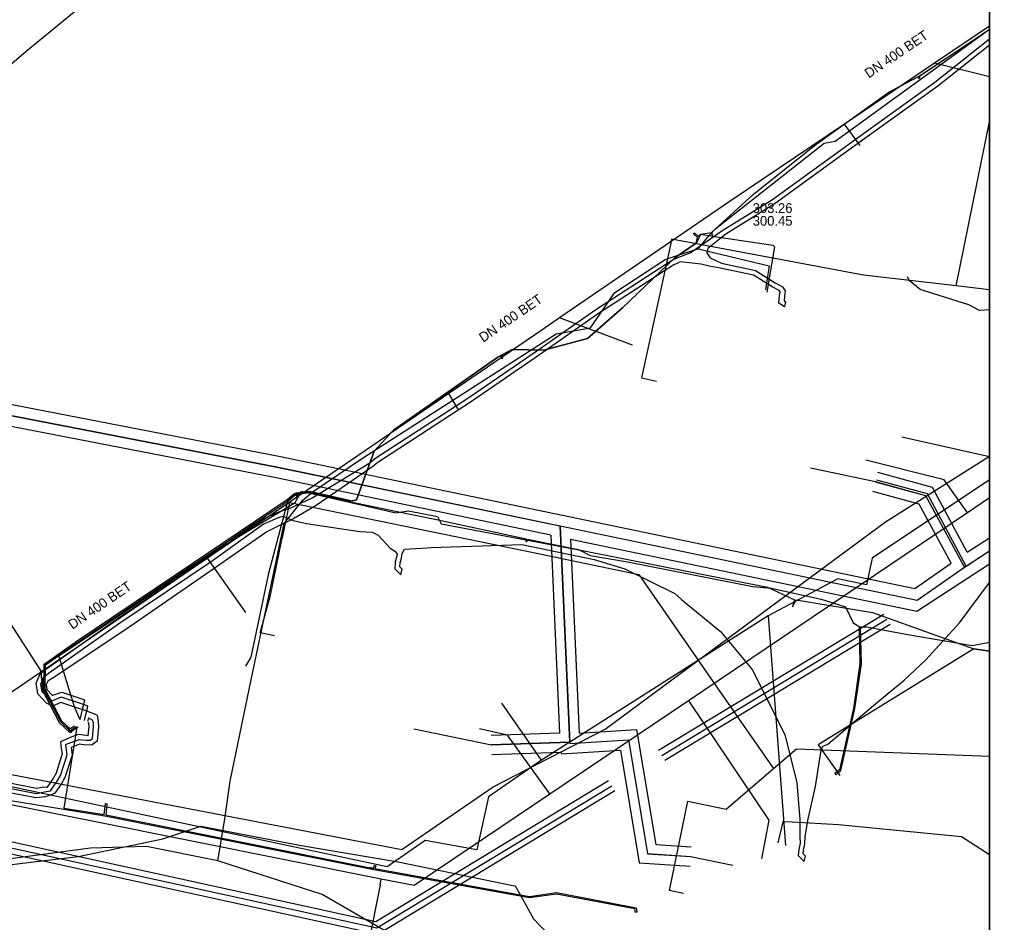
# Model space of a CAD drawing. Extents: x -598233 to -596890, y -1157848 to -1156431.
# Drawn here: x -596970.3 to -596890.5, y -1156694.6 to -1156620.3 of the extents above; entities that cross this region are included whole.
import ezdxf

# ---------------------------------------------------------------- set-up
doc = ezdxf.new("R2010")
doc.units = 0
for name, color, linetype in [('Vrstva 12', 7, 'Continuous'), ('Vrstva 13', 7, 'Continuous'), ('Vrstva 16', 7, 'Continuous'), ('Vrstva 19', 7, 'Continuous'), ('Vrstva 37', 7, 'Continuous'), ('Vrstva 38', 7, 'Continuous'), ('Vrstva 42', 7, 'Continuous'), ('Vrstva 55', 7, 'Continuous'), ('Vrstva 58', 7, 'Continuous'), ('Vrstva 60', 7, 'Continuous'), ('Vrstva 9', 7, 'Continuous'), ('zajmove_uzemi', 7, 'Continuous')]:
    doc.layers.add(name, color=color, linetype=linetype)

msp = doc.modelspace()

# ---------------------------------------------------------------- linework, layer by layer
at = {"layer": 'Vrstva 12'}
for p, q in [((-596890.462, -1156628.613), (-596890.48, -1156628.7)), ((-596890.462, -1156642.532), (-596893.2, -1156642.21))]:
    msp.add_line(p, q, dxfattribs=at)
for points in [[(-596893.2, -1156642.21), (-596890.48, -1156628.7)], [(-596916.727, -1156638.834), (-596919.1, -1156649.78), (-596917.88, -1156650.03)], [(-596893.2, -1156642.21), (-596900.84, -1156641.31), (-596916.626, -1156638.369), (-596916.727, -1156638.834)], [(-596948.6, -1156662.66), (-596948.05, -1156660.02), (-596928.14, -1156664.12), (-596919.32, -1156665.94), (-596913.09, -1156674.93), (-596908.53, -1156681.51), (-596908.24, -1156681.92)], [(-596949.31, -1156670.99), (-596950.49, -1156670.75), (-596949.64, -1156667.65), (-596948.66, -1156662.96), (-596948.6, -1156662.66)], [(-596908.24, -1156681.92), (-596906.34, -1156680.3), (-596890.462, -1156680.897)], [(-596915.64, -1156692.19), (-596916.79, -1156691.95), (-596915.3, -1156684.6), (-596912.15, -1156685.24), (-596908.24, -1156681.92)], [(-596978.48, -1156691.48), (-596975.31, -1156690.33), (-596965.47, -1156689.14), (-596958.49, -1156687.7), (-596955.37, -1156686.64), (-596947.26, -1156688.21), (-596945.47, -1156688.51)], [(-596945.47, -1156688.51), (-596939.14, -1156689.58), (-596929.7, -1156691.53)], [(-596929.7, -1156691.53), (-596929.49, -1156691.57), (-596928.9, -1156692.64)], [(-596928.9, -1156692.64), (-596927.99, -1156694.27), (-596924.9, -1156697.52), (-596921.41, -1156700.73), (-596919.34, -1156702.7), (-596918.68, -1156703.63), (-596917.78, -1156704.19), (-596916.85, -1156706.16), (-596914.16, -1156711.34), (-596910.89, -1156714.39), (-596904.56, -1156718.91), (-596900.16, -1156722.49), (-596897.928, -1156726.658)]]:
    msp.add_lwpolyline(points, dxfattribs=at)
at = {"layer": 'Vrstva 13'}
for p, q in [((-596940.522, -1156691), (-596999.171, -1156679.242)), ((-596940.617, -1156691.482), (-596940.522, -1156691))]:
    msp.add_line(p, q, dxfattribs=at)
for points in [[(-596892.293, -1156660.877), (-596892.343, -1156660.8), (-596894.197, -1156658.147), (-596900.657, -1156656.545)], [(-596890.462, -1156659.644), (-596892.293, -1156660.877), (-596915.238, -1156676.335), (-596926.647, -1156684.02), (-596934.627, -1156689.398), (-596937.81, -1156691.544), (-596940.522, -1156691)], [(-596915.238, -1156676.335), (-596915.152, -1156676.461), (-596908.641, -1156686.153), (-596909.219, -1156689.349)], [(-596926.647, -1156684.02), (-596926.732, -1156683.886), (-596930.119, -1156679.171), (-596932.423, -1156678.632)], [(-596940.617, -1156691.482), (-596948.106, -1156729.131), (-596948.339, -1156730.315), (-596948.53, -1156731.238)]]:
    msp.add_lwpolyline(points, dxfattribs=at)
at = {"layer": 'Vrstva 16'}
msp.add_line((-596897.68, -1156654.63), (-596890.462, -1156656.246), dxfattribs=at)
for points in [[(-596890.462, -1156658.167), (-596900.13, -1156664.59), (-596900.58, -1156666.8), (-596902.94, -1156666.3), (-596908.67, -1156669.34), (-596927.34, -1156681.23), (-596931.7, -1156684.23), (-596932.66, -1156688.6), (-596936.9, -1156687.83), (-596940.03, -1156690), (-596981.04, -1156681.27), (-596997, -1156677.6), (-597016.06, -1156671.9), (-597015.61, -1156669.9)], [(-596908.67, -1156669.34), (-596907.25, -1156688.25)], [(-596927.34, -1156681.23), (-596930.61, -1156676.54)]]:
    msp.add_lwpolyline(points, dxfattribs=at)
at = {"layer": 'Vrstva 19'}
msp.add_lwpolyline([(-596990.71, -1156678.66), (-596990.29, -1156678.69), (-596990.15, -1156678.37), (-596980.83, -1156680.51), (-596938.83, -1156688.56), (-596931.31, -1156683.41), (-596922.1, -1156678.66), (-596905.13, -1156666.11), (-596899.02, -1156661.61), (-596890.462, -1156656.215)], dxfattribs=at)
at = {"layer": 'Vrstva 37'}
for p, q in [((-596899.863, -1156658.336), (-596905.212, -1156657.21)), ((-596925.801, -1156661.951), (-596925.013, -1156679.762)), ((-596925.801, -1156661.951), (-596925.006, -1156679.756)), ((-596892.541, -1156665.348), (-596890.462, -1156664)), ((-596892.39, -1156665.247), (-596890.462, -1156663.999)), ((-596917.435, -1156680.833), (-596898.915, -1156669.625)), ((-596931.449, -1156679.981), (-596937.839, -1156678.674)), ((-596925.013, -1156679.762), (-596931.449, -1156679.981)), ((-596925.013, -1156679.762), (-596931.449, -1156679.981)), ((-596915.061, -1156689.154), (-596911.603, -1156689.859))]:
    msp.add_line(p, q, dxfattribs=at)
for points in [[(-597000.648, -1156655.849), (-596996.215, -1156656.976), (-596994.547, -1156648.298), (-596948.98, -1156657.107), (-596925.801, -1156661.951)], [(-597000.648, -1156655.849), (-596996.215, -1156656.976), (-596994.547, -1156648.298), (-596948.978, -1156657.138), (-596925.826, -1156661.946)], [(-596892.39, -1156665.247), (-596895.582, -1156659.321), (-596899.74, -1156658.191)], [(-596892.541, -1156665.348), (-596895.705, -1156659.466), (-596899.863, -1156658.336)], [(-596892.541, -1156665.348), (-596895.705, -1156659.466), (-596899.863, -1156658.336)], [(-596925.826, -1156661.946), (-596925.039, -1156679.73), (-596931.475, -1156679.949)], [(-596925.801, -1156661.951), (-596896.426, -1156668.05), (-596892.541, -1156665.348)], [(-596925.801, -1156661.951), (-596896.426, -1156668.05), (-596892.541, -1156665.348)], [(-596925.013, -1156679.762), (-596925.003, -1156679.859), (-596920.178, -1156679.547), (-596918.606, -1156688.918), (-596915.061, -1156689.154)], [(-596925.013, -1156679.762), (-596925.002, -1156679.861), (-596920.178, -1156679.547), (-596918.606, -1156688.918), (-596915.061, -1156689.154)], [(-596925.006, -1156679.756), (-596924.996, -1156679.853), (-596920.171, -1156679.541), (-596918.599, -1156688.912), (-596915.054, -1156689.148)], [(-596994.927, -1156683.194), (-596990.833, -1156684.091), (-596940.89, -1156695.028), (-596921.559, -1156683.329)]]:
    msp.add_lwpolyline(points, dxfattribs=at)
at = {"layer": 'Vrstva 38'}
for p, q in [((-596926.568, -1156662.71), (-596925.848, -1156678.989)), ((-596892.295, -1156664.116), (-596890.462, -1156662.927)), ((-596924.952, -1156663.046), (-596924.246, -1156679.008)), ((-596924.952, -1156663.046), (-596896.461, -1156668.962)), ((-596896.461, -1156668.962), (-596890.462, -1156665.073)), ((-596917.694, -1156680.405), (-596899.174, -1156669.197)), ((-596898.656, -1156670.053), (-596917.176, -1156681.261)), ((-596925.848, -1156678.989), (-596931.476, -1156679.181)), ((-596925.732, -1156680.587), (-596931.422, -1156680.781))]:
    msp.add_line(p, q, dxfattribs=at)
for points in [[(-597000.426, -1156654.977), (-596996.919, -1156655.868), (-596995.261, -1156647.243), (-596948.803, -1156656.225), (-596925.617, -1156661.07)], [(-596926.568, -1156662.71), (-596949.157, -1156657.989), (-596993.833, -1156649.353), (-596995.511, -1156658.084), (-597000.907, -1156656.712)], [(-596892.295, -1156664.116), (-596895.163, -1156658.784), (-596899.653, -1156657.564)], [(-596893.632, -1156665.01), (-596896.247, -1156660.148), (-596900.073, -1156659.108)], [(-596925.618, -1156661.07), (-596896.622, -1156667.09), (-596893.632, -1156665.01)], [(-596924.246, -1156679.008), (-596919.509, -1156678.702), (-596917.922, -1156688.162), (-596915.008, -1156688.356)], [(-596925.732, -1156680.587), (-596925.72, -1156680.707), (-596920.847, -1156680.392), (-596919.29, -1156689.674), (-596915.114, -1156689.952)], [(-596994.82, -1156682.706), (-596940.978, -1156694.497), (-596921.818, -1156682.901)], [(-596921.3, -1156683.757), (-596940.802, -1156695.559), (-596995.034, -1156683.682)]]:
    msp.add_lwpolyline(points, dxfattribs=at)
at = {"layer": 'Vrstva 42'}
for p, q in [((-596925.8, -1156661.95), (-596925.01, -1156679.76)), ((-596892.39, -1156665.25), (-596890.462, -1156664.005)), ((-596925.01, -1156679.76), (-596931.45, -1156679.98))]:
    msp.add_line(p, q, dxfattribs=at)
for points in [[(-596963.909, -1156677.528), (-596964.756, -1156677.187), (-596965.117, -1156677.042), (-596965.123, -1156677.04), (-596965.406, -1156676.965), (-596966.895, -1156676.47), (-596967.558, -1156676.78), (-596968.077, -1156676.525), (-596968.787, -1156675.768), (-596968.909, -1156674.892), (-596968.581, -1156674.128), (-596968.148, -1156673.759), (-596962.174, -1156669.532), (-596954.836, -1156664.613), (-596950.431, -1156661.447), (-596948.935, -1156660.802), (-596948.026, -1156660.486), (-596946.204, -1156659.652), (-596941.45, -1156656.746), (-596941.041, -1156656.408), (-596933.309, -1156651.387), (-596927.713, -1156647.549), (-596922.859, -1156644.15), (-596916.632, -1156640.105), (-596916.164, -1156639.903), (-596915.114, -1156639.47), (-596912.404, -1156637.606), (-596908.329, -1156635.083), (-596901.831, -1156630.371), (-596894.964, -1156625.441), (-596890.462, -1156621.888)], [(-596890.462, -1156622.397), (-596894.724, -1156625.761), (-596901.597, -1156630.695), (-596908.105, -1156635.415), (-596912.176, -1156637.936), (-596913.658, -1156639.122), (-596913.743, -1156639.495), (-596913.455, -1156639.906), (-596912.525, -1156640.345), (-596909.731, -1156640.933), (-596908.1, -1156641.961), (-596907.51, -1156642.289), (-596907.271, -1156642.618), (-596907.345, -1156643.04), (-596907.377, -1156643.421), (-596907.257, -1156643.509), (-596907.312, -1156643.754)], [(-596907.312, -1156643.754), (-596907.351, -1156643.936), (-596907.793, -1156643.611), (-596907.743, -1156642.99), (-596907.695, -1156642.716), (-596907.782, -1156642.595), (-596908.304, -1156642.305), (-596909.883, -1156641.309), (-596912.631, -1156640.731), (-596913.537, -1156640.57), (-596914.198, -1156640.416), (-596915.923, -1156640.231), (-596916.118, -1156640.323), (-596916.44, -1156640.457), (-596922.635, -1156644.482), (-596927.485, -1156647.877), (-596933.087, -1156651.719), (-596940.803, -1156656.73), (-596941.212, -1156657.068), (-596945.868, -1156660.273), (-596947.801, -1156661.4), (-596947.898, -1156661.444), (-596948.726, -1156661.82), (-596949.928, -1156662.441), (-596954.255, -1156665.458), (-596961.62, -1156670.534), (-596967.61, -1156674.49), (-596967.967, -1156674.727), (-596968.085, -1156675.002), (-596968.029, -1156675.406), (-596967.597, -1156675.867), (-596967.542, -1156675.882), (-596966.81, -1156675.626), (-596965.146, -1156676.188), (-596964.928, -1156676.259), (-596965.022, -1156676.65), (-596965.117, -1156677.042), (-596965.319, -1156677.879)], [(-597000.65, -1156655.85), (-596996.22, -1156656.98), (-596994.55, -1156648.3), (-596948.98, -1156657.14), (-596925.83, -1156661.95)], [(-596892.39, -1156665.25), (-596895.58, -1156659.32), (-596899.74, -1156658.19)], [(-596892.54, -1156665.35), (-596895.7, -1156659.47), (-596899.86, -1156658.34)], [(-596964.947, -1156677.968), (-596964.818, -1156677.461), (-596964.756, -1156677.187), (-596964.662, -1156676.77), (-596965.022, -1156676.65), (-596966.858, -1156676.038), (-596967.563, -1156676.326), (-596967.837, -1156676.196), (-596968.408, -1156675.587), (-596968.53, -1156674.976), (-596968.25, -1156674.372), (-596967.888, -1156674.063), (-596961.948, -1156669.862), (-596954.608, -1156664.941), (-596950.233, -1156661.797), (-596948.85, -1156661.198), (-596948.61, -1156661.145), (-596947.898, -1156661.444), (-596947.756, -1156661.504), (-596946.657, -1156661.744), (-596942.284, -1156662.42), (-596941.279, -1156662.473), (-596940.775, -1156662.698), (-596939.786, -1156663.772), (-596939.404, -1156664.028), (-596939.202, -1156664.247), (-596939.256, -1156664.524), (-596939.37, -1156664.921), (-596939.39, -1156665.469), (-596938.909, -1156665.985), (-596938.849, -1156665.7), (-596938.803, -1156665.499), (-596938.984, -1156665.315), (-596938.972, -1156664.985), (-596938.862, -1156664.604), (-596938.789, -1156664.209), (-596938.616, -1156663.868), (-596936.74, -1156663.765), (-596936.405, -1156663.712), (-596928.958, -1156663.488), (-596923.008, -1156664.706), (-596920.488, -1156665.474), (-596916.374, -1156667.504), (-596915.816, -1156668.004), (-596912.601, -1156670.636), (-596910.011, -1156673.762), (-596907.32, -1156679.108), (-596906.327, -1156683.082), (-596906.066, -1156686.097), (-596906.066, -1156687.516), (-596906.057, -1156688.051), (-596906.158, -1156688.576), (-596906.203, -1156689.064), (-596905.729, -1156689.57), (-596905.675, -1156689.329)], [(-596925.83, -1156661.95), (-596925.04, -1156679.73), (-596931.47, -1156679.95)], [(-596925.8, -1156661.95), (-596896.43, -1156668.05), (-596892.54, -1156665.35)], [(-596905.675, -1156689.329), (-596905.617, -1156689.107), (-596905.789, -1156688.922), (-596905.762, -1156688.632), (-596905.659, -1156688.095), (-596905.635, -1156687.541), (-596905.421, -1156686.188), (-596904.795, -1156683.387), (-596904.335, -1156680.403), (-596904.189, -1156680.072), (-596903.761, -1156679.911), (-596899.657, -1156676.416), (-596897.498, -1156674.632), (-596895.75, -1156672.985), (-596892.928, -1156669.909), (-596890.462, -1156666.603)], [(-596963.909, -1156677.528), (-596963.803, -1156678.065), (-596963.785, -1156678.489), (-596963.909, -1156679.645), (-596964.317, -1156679.968), (-596964.824, -1156679.989), (-596965.337, -1156679.912), (-596966.043, -1156680.174), (-596965.962, -1156680.805), (-596966.549, -1156682.646), (-596966.86, -1156683.19), (-596967.411, -1156683.964), (-596968.155, -1156684.231), (-596968.95, -1156684.323), (-596974.442, -1156683.278)], [(-596974.38, -1156682.883), (-596968.888, -1156683.954), (-596968.225, -1156683.837), (-596967.737, -1156683.732), (-596967.19, -1156682.942), (-596966.917, -1156682.484), (-596966.371, -1156680.771), (-596966.454, -1156680.184), (-596966.481, -1156679.939), (-596966.364, -1156679.88), (-596965.387, -1156679.525), (-596964.81, -1156679.588), (-596964.463, -1156679.574), (-596964.289, -1156679.436), (-596964.186, -1156678.476), (-596964.2, -1156678.142), (-596964.28, -1156677.918), (-596964.605, -1156677.779), (-596964.685, -1156678.029)], [(-596964.668, -1156678.12), (-596964.619, -1156678.131), (-596964.597, -1156678.219), (-596964.587, -1156678.463), (-596964.669, -1156679.227), (-596964.796, -1156679.187), (-596965.436, -1156679.117), (-596965.971, -1156679.312), (-596966.904, -1156679.709), (-596966.859, -1156680.251), (-596966.772, -1156680.697), (-596967.263, -1156682.29), (-596967.524, -1156682.722), (-596968.049, -1156683.465), (-596968.295, -1156683.443), (-596968.884, -1156683.547), (-596974.318, -1156682.488)], [(-596966.261, -1156678.479), (-596966.222, -1156678.758), (-596966.047, -1156678.951), (-596965.975, -1156678.863)], [(-596925.01, -1156679.76), (-596925, -1156679.85), (-596920.17, -1156679.54), (-596918.6, -1156688.91), (-596915.05, -1156689.15)], [(-596925.01, -1156679.76), (-596925, -1156679.86), (-596920.18, -1156679.55), (-596918.61, -1156688.92), (-596915.06, -1156689.15)]]:
    msp.add_lwpolyline(points, dxfattribs=at)
at = {"layer": 'Vrstva 55'}
for points in [[(-596972.3, -1156625.05), (-596969.73, -1156622.9), (-596962.75, -1156617.14)], [(-596965.6, -1156678.47), (-596966.12, -1156678.8), (-596966.89, -1156678.08), (-596968.289, -1156675.407), (-596968.27, -1156673.329), (-596965.819, -1156671.587), (-596965.61, -1156671.68), (-596965.716, -1156671.515), (-596957.343, -1156665.89), (-596948.256, -1156659.782), (-596947.62, -1156659.267), (-596947.433, -1156659.553), (-596947.35, -1156659.57), (-596947.333, -1156659.487), (-596947.51, -1156659.216), (-596946.387, -1156659.089), (-596942.884, -1156659.887), (-596942.55, -1156659.8), (-596941.11, -1156655.79), (-596939.5, -1156654.08), (-596930.93, -1156648.06), (-596930.713, -1156647.948), (-596930.62, -1156648.142), (-596930.54, -1156648.17), (-596930.512, -1156648.09), (-596930.607, -1156647.892), (-596929.76, -1156647.44), (-596927.13, -1156647.48), (-596923.56, -1156646.54), (-596920.66, -1156644), (-596916.33, -1156639.87), (-596914.61, -1156638.69), (-596914.505, -1156638.217), (-596914.796, -1156637.955), (-596914.8, -1156637.87), (-596914.715, -1156637.866), (-596914.441, -1156638.114), (-596914.23, -1156637.96), (-596913.34, -1156637.81), (-596909.93, -1156634.68), (-596909.2, -1156634.12), (-596904.76, -1156630.57), (-596898.74, -1156626.26), (-596896.374, -1156624.999), (-596896.285, -1156625.103), (-596896.2, -1156625.11), (-596896.193, -1156625.025), (-596896.269, -1156624.937), (-596891.76, -1156621.97), (-596890.462, -1156621.081)], [(-596890.462, -1156644.171), (-596891.28, -1156644.22), (-596892.17, -1156643.77), (-596896.17, -1156642.49), (-596897.08, -1156641.76), (-596897.23, -1156641.46)], [(-596965.748, -1156678.422), (-596966.106, -1156678.649), (-596966.793, -1156678.006), (-596968.169, -1156675.378), (-596968.15, -1156673.391), (-596965.686, -1156671.639), (-596959.12, -1156667.228), (-596957.277, -1156665.99), (-596954.134, -1156663.877), (-596951.051, -1156661.805), (-596948.184, -1156659.878), (-596947.833, -1156659.595), (-596947.516, -1156659.338), (-596946.393, -1156659.211), (-596943.023, -1156659.979), (-596939.48, -1156660.7), (-596935.96, -1156661.41), (-596928.609, -1156663.017), (-596928.625, -1156663.205), (-596928.57, -1156663.27), (-596928.505, -1156663.215), (-596928.491, -1156663.042), (-596924.29, -1156663.88), (-596923.32, -1156664.37), (-596920.25, -1156664.91), (-596909.95, -1156666.92), (-596908.43, -1156667.07), (-596904.33, -1156667.97), (-596902.33, -1156668.6), (-596901.69, -1156669.92), (-596901.201, -1156670.222), (-596901.13, -1156673.296), (-596901.659, -1156676.959), (-596902.814, -1156682.006), (-596903.18, -1156682.296), (-596903.19, -1156682.38), (-596903.106, -1156682.39), (-596902.706, -1156682.074), (-596901.541, -1156676.981), (-596901.01, -1156673.304), (-596901.08, -1156670.258), (-596900.58, -1156670.24), (-596897.18, -1156670.88), (-596891.91, -1156671.78), (-596890.462, -1156671.509)], [(-596965.29, -1156677.9), (-596965.75, -1156676.84), (-596967.04, -1156672.65), (-596953.544, -1156663.61), (-596947.613, -1156660.015), (-596947.07, -1156659.08), (-596939.31, -1156660.87), (-596938.27, -1156660.72), (-596935.89, -1156661.17), (-596935.59, -1156661.77), (-596923.81, -1156664), (-596908.75, -1156666.98), (-596906.52, -1156668.03), (-596906.67, -1156668.62), (-596906.37, -1156668.03), (-596900.11, -1156669.07), (-596891.76, -1156672.05), (-596890.462, -1156672.259)], [(-596965.6, -1156678.47), (-596966.12, -1156678.8), (-596966.89, -1156678.08), (-596968.289, -1156675.407), (-596968.54, -1156673.84), (-596974.43, -1156664.72), (-596974.89, -1156664.58), (-596978.41, -1156663.08), (-596979.9, -1156662.59), (-596982.63, -1156664.4), (-596985.57, -1156668.83), (-596989.58, -1156673.24), (-596991.79, -1156675.42), (-596994.05, -1156677.85), (-596993.75, -1156680.67), (-596993.714, -1156680.787)], [(-596965.453, -1156678.519), (-596966.134, -1156678.951), (-596966.987, -1156678.154), (-596968.336, -1156675.576), (-596968.54, -1156673.84), (-596974.43, -1156664.72)], [(-596890.462, -1156672.259), (-596891.76, -1156672.05), (-596904.58, -1156679.95), (-596902.79, -1156682.49)], [(-596965.574, -1156678.495), (-596966.629, -1156685.17), (-596963.312, -1156685.691), (-596963.205, -1156684.791), (-596963.06, -1156684.82), (-596963.095, -1156684.889), (-596963.194, -1156685.712), (-596941.169, -1156690.121), (-596941.454, -1156690.061), (-596941.169, -1156690.121), (-596941.076, -1156689.869), (-596940.964, -1156689.911), (-596941.049, -1156690.144), (-596928.319, -1156692.429), (-596926.089, -1156692.119), (-596919.537, -1156693.359), (-596919.481, -1156693.731), (-596919.599, -1156693.749), (-596919.643, -1156693.461), (-596926.091, -1156692.241), (-596928.321, -1156692.551), (-596941.141, -1156690.249), (-596963.271, -1156685.819), (-596966.648, -1156685.288), (-596978.47, -1156683.37)]]:
    msp.add_lwpolyline(points, dxfattribs=at)
at = {"layer": 'Vrstva 58'}
msp.add_line((-596913.34, -1156637.81), (-596913.27, -1156638.1), dxfattribs=at)
for points in [[(-596914.43, -1156639.14), (-596913.55, -1156638.07), (-596912.98, -1156637.48), (-596909.62, -1156634.81), (-596904.08, -1156630.47), (-596903.17, -1156630.3), (-596890.462, -1156621.089)], [(-596913.34, -1156637.81), (-596909.93, -1156634.68), (-596909.2, -1156634.12), (-596904.76, -1156630.57), (-596898.74, -1156626.26), (-596896.32, -1156624.97), (-596891.76, -1156621.97), (-596890.462, -1156621.081)], [(-596914.23, -1156637.96), (-596914.61, -1156638.69), (-596916.33, -1156639.87), (-596920.66, -1156644), (-596923.56, -1156646.54), (-596927.13, -1156647.48), (-596929.76, -1156647.44), (-596930.93, -1156648.06), (-596939.5, -1156654.08), (-596941.11, -1156655.79), (-596942.55, -1156659.8), (-596943.01, -1156659.92), (-596946.39, -1156659.15), (-596947.54, -1156659.28), (-596948.22, -1156659.83), (-596949.83, -1156665.98), (-596951.26, -1156672.75), (-596951.69, -1156673.48)], [(-596914.23, -1156637.96), (-596913.34, -1156637.81)], [(-596914.23, -1156637.96), (-596913.27, -1156638.1)], [(-596913.27, -1156638.1), (-596908.3, -1156638.84), (-596908.17, -1156638.99), (-596908.79, -1156642.73)], [(-596946.12, -1156659.12), (-596942.07, -1156656.37), (-596926.14, -1156646.15), (-596923.31, -1156645.65), (-596921.29, -1156642.74), (-596917.17, -1156640.04), (-596915.67, -1156639.55), (-596914.43, -1156639.14)], [(-596914.43, -1156639.14), (-596908.61, -1156640.56), (-596908.91, -1156642.54)], [(-596953.96, -1156689.49), (-596953.41, -1156686.24), (-596952.94, -1156682.95), (-596951.2, -1156674.47), (-596948.5, -1156661.75), (-596946.97, -1156659.82), (-596946.12, -1156659.12)], [(-596890.462, -1156689.018), (-596892.77, -1156687.53), (-596902.89, -1156686.54), (-596906.7, -1156686.32), (-596907.48, -1156686.29), (-596907.9, -1156688.01)], [(-596953.96, -1156689.49), (-596959.84, -1156688.32), (-596964.44, -1156688.45), (-596979.72, -1156690.49), (-596981.92, -1156690.04), (-596992.49, -1156687.9), (-596993.41, -1156687.91), (-596995.83, -1156687.81), (-596999.76, -1156689.35), (-597000.99, -1156689.37), (-597002.09, -1156690), (-597003.22, -1156692.51), (-597004.23, -1156692.32)], [(-596923.37, -1156723.25), (-596924.46, -1156714.56), (-596927.7, -1156705.2), (-596929.01, -1156702.44), (-596930.76, -1156700.27), (-596933.49, -1156699.15), (-596945.39, -1156692.27), (-596953.96, -1156689.49)]]:
    msp.add_lwpolyline(points, dxfattribs=at)
at = {"layer": 'Vrstva 60'}
msp.add_lwpolyline([(-596890.462, -1157848.461), (-596890.462, -1156430.856)], dxfattribs=at)
at = {"layer": 'Vrstva 9'}
for p, q in [((-596890.462, -1156625.008), (-596894.986, -1156623.891)), ((-596901.105, -1156630.647), (-596902.388, -1156628.887)), ((-596919.835, -1156647.088), (-596925.85, -1156644.836)), ((-596934.16, -1156652.405), (-596934.967, -1156651.064)), ((-596951.65, -1156669.08), (-596954.817, -1156664.616))]:
    msp.add_line(p, q, dxfattribs=at)
for points in [[(-596890.462, -1156620.838), (-596894.986, -1156623.891), (-596902.388, -1156628.887), (-596911.798, -1156635.237)], [(-596911.798, -1156635.237), (-596925.85, -1156644.836), (-596927.316, -1156645.838), (-596934.967, -1156651.064), (-596942.865, -1156656.459)], [(-596942.865, -1156656.459), (-596954.816, -1156664.615), (-596954.817, -1156664.616), (-596967.007, -1156672.936), (-596967.008, -1156672.936), (-596973.96, -1156677.681)]]:
    msp.add_lwpolyline(points, dxfattribs=at)
at = {"layer": 'zajmove_uzemi'}
msp.add_lwpolyline([(-598232.89, -1156430.856), (-596890.462, -1156430.856), (-596890.462, -1157848.461), (-598232.89, -1157848.461)], close=True, dxfattribs=at)

# ---------------------------------------------------------------- texts
at = {"layer": 'Vrstva 12'}
for rotation, p in [(34.03369, (-596900.408, -1156625.149)), (34.32017, (-596932.133, -1156646.882)), (34.32017, (-596965.935, -1156670.499))]:
    msp.add_text('DN 400 BET', height=0.8, rotation=rotation, dxfattribs=at).set_placement(p)
for s, p in [('303.26', (-596909.953, -1156636.2)), ('300.45', (-596909.953, -1156637.25))]:
    msp.add_text(s, height=0.8, dxfattribs=at).set_placement(p)

doc.saveas('drawing.dxf')
